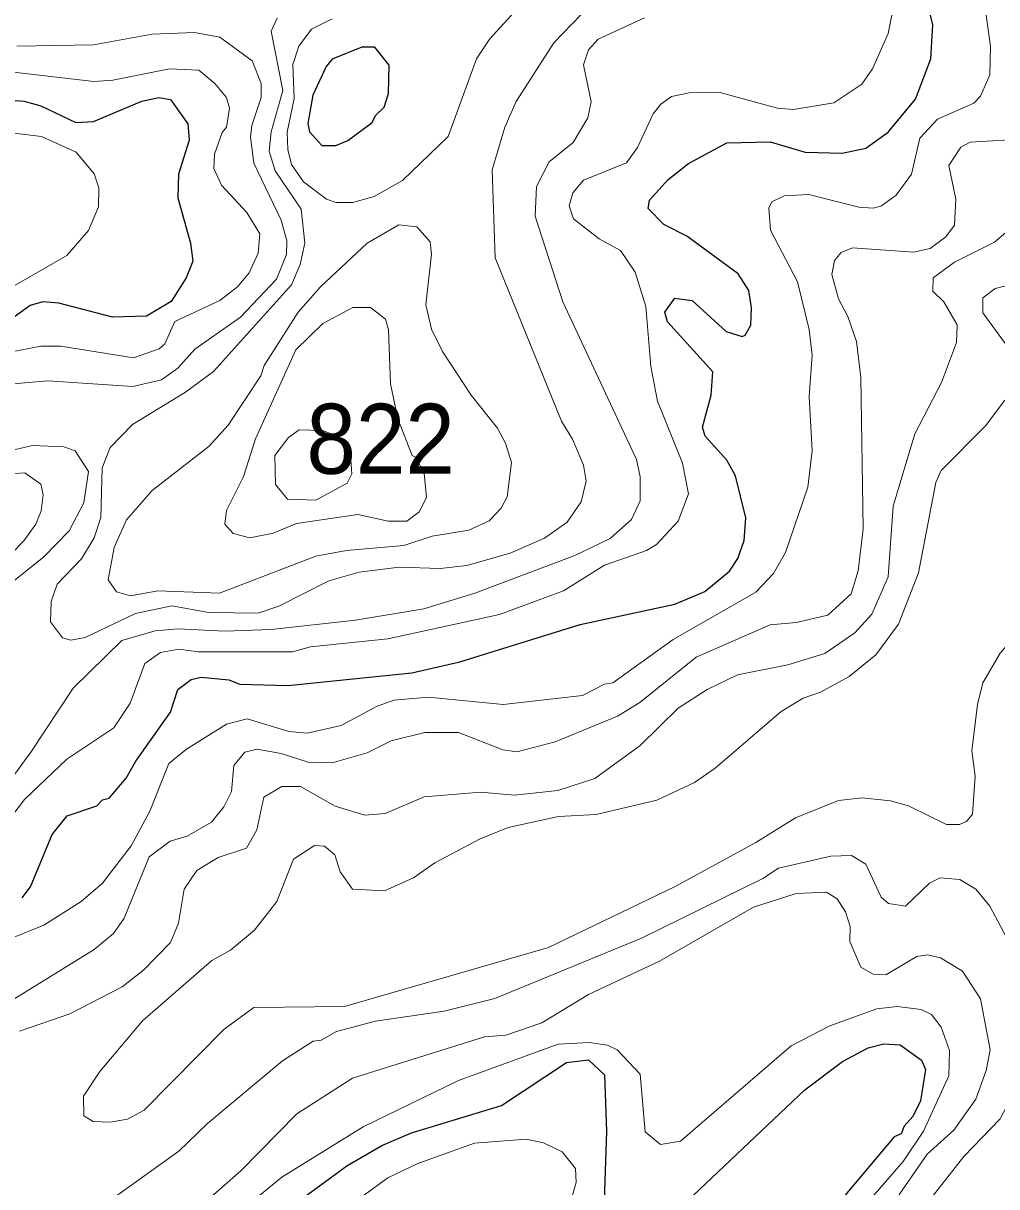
# Model space of a CAD drawing. Extents: x 763.2 to 816.8, y 7896.5 to 7952.7.
# Drawn here: x 765.256 to 767.48, y 7901.566 to 7904.224 of the extents above; entities that cross this region are included whole.
import ezdxf

# ---------------------------------------------------------------- set-up
doc = ezdxf.new("R2010")
doc.units = 0
doc.header["$LTSCALE"] = 0.064
doc.layers.add('1', color=7, linetype='Continuous', lineweight=25)
doc.layers.add('2', color=7, linetype='Continuous', lineweight=13)
doc.layers.add('21', color=7, linetype='Continuous')

msp = doc.modelspace()

# ---------------------------------------------------------------- linework, layer by layer
at = {"layer": '1'}
for points in [[(765.6395, 7902.7247), (765.6623, 7902.7301), (765.7256, 7902.7238), (765.751, 7902.7138), (765.8604, 7902.7106), (766.1439, 7902.74), (766.2539, 7902.7649), (766.5283, 7902.8502), (766.7446, 7902.8967), (766.8135, 7902.9259), (766.8698, 7902.9724), (766.889, 7903.0014), (766.9033, 7903.0424), (766.9071, 7903.0937), (766.8833, 7903.1903), (766.8634, 7903.2261), (766.8142, 7903.2803), (766.8079, 7903.3014), (766.8282, 7903.3744), (766.8315, 7903.428), (766.7278, 7903.5422), (766.7219, 7903.5643), (766.7448, 7903.5958), (766.7847, 7903.5904), (766.8622, 7903.5197), (766.8983, 7903.5087), (766.9058, 7903.5116), (766.9185, 7903.5339), (766.9202, 7903.574), (766.9136, 7903.6133), (766.8896, 7903.6515), (766.7723, 7903.7373), (766.7199, 7903.7639), (766.6839, 7903.8007), (766.6872, 7903.8197), (766.7298, 7903.8674), (766.7757, 7903.9036), (766.8638, 7903.9508), (766.9623, 7903.9529), (767.0428, 7903.9299), (767.1273, 7903.9271), (767.1816, 7903.9385), (767.2319, 7903.9755), (767.2945, 7904.0509), (767.3297, 7904.1427), (767.3344, 7904.2201), (767.311, 7904.3166)], [(765.0943, 7904.0586), (765.2579, 7904.0463), (765.2959, 7904.0352), (765.3763, 7903.9974), (765.4167, 7903.9996), (765.5267, 7904.0459), (765.5655, 7904.0546), (765.5922, 7904.0496), (765.6321, 7903.9941), (765.6348, 7903.9571), (765.6107, 7903.8789), (765.6089, 7903.8254), (765.6382, 7903.722), (765.6433, 7903.6804), (765.6285, 7903.6423), (765.5939, 7903.5882), (765.538, 7903.5547), (765.4603, 7903.5522), (765.3377, 7903.5849), (765.3008, 7903.5878), (765.2721, 7903.5795), (765.152, 7903.4928)], [(765.4522, 7902.4538), (765.4909, 7902.4991), (765.5131, 7902.5378), (765.5926, 7902.6502), (765.6093, 7902.7022), (765.6395, 7902.7247)], [(765.2539, 7902.226), (765.2723, 7902.251), (765.3219, 7902.3708), (765.3566, 7902.4131), (765.424, 7902.4359), (765.4372, 7902.4499), (765.4522, 7902.4538)], [(766.744, 7901.5053), (767.042, 7901.7868), (767.1283, 7901.8519), (767.1867, 7901.883), (767.2227, 7901.8919), (767.2596, 7901.8898), (767.3083, 7901.8553), (767.3178, 7901.8338), (767.3064, 7901.7623), (767.2884, 7901.7261), (767.2689, 7901.7045), (767.2619, 7901.6869), (767.2459, 7901.6798), (767.1171, 7901.5265)], [(765.6599, 7901.3677), (765.9953, 7901.6133), (766.0757, 7901.6602), (766.143, 7901.6888), (766.3491, 7901.7511), (766.4971, 7901.8494), (766.5479, 7901.8554), (766.5842, 7901.8213), (766.5884, 7901.6916), (766.5836, 7901.5345)]]:
    msp.add_lwpolyline(points, dxfattribs=at)
msp.add_lwpolyline([(766.0903, 7904.0638), (766.0918, 7904.1286), (766.0593, 7904.1693), (766.0297, 7904.1697), (765.962, 7904.1424), (765.9482, 7904.1255), (765.9179, 7904.0597), (765.9065, 7903.9948), (765.9103, 7903.9763), (765.9385, 7903.9449), (765.9703, 7903.9449), (765.9976, 7903.956), (766.0536, 7903.997), (766.061, 7904.0135), (766.0807, 7904.0325)], close=True, dxfattribs=at)
at = {"layer": '2'}
for points in [[(767.1084, 7904.0419), (767.1723, 7904.0851), (767.1967, 7904.1197), (767.2323, 7904.2004), (767.2556, 7904.3194), (767.2476, 7904.3788)], [(767.4496, 7904.2913), (767.4659, 7904.1715), (767.4642, 7904.1064), (767.4432, 7904.0573), (767.4281, 7904.0417), (767.3448, 7904.005), (767.3049, 7903.9619), (767.2854, 7903.8796), (767.2506, 7903.8312), (767.2168, 7903.8071), (767.1991, 7903.8018), (767.165, 7903.8038), (767.0511, 7903.8329), (766.995, 7903.83), (766.9667, 7903.8163), (766.9599, 7903.8018), (766.9631, 7903.7515), (767.0251, 7903.633), (767.0516, 7903.5246), (767.0583, 7903.4655), (767.0518, 7903.3712), (767.0584, 7903.2471), (767.0488, 7903.1638), (766.9978, 7903.0152), (766.9704, 7902.9665), (766.9301, 7902.9243), (766.7409, 7902.8164), (766.6029, 7902.7174), (766.5842, 7902.7138), (766.5339, 7902.6878), (766.3524, 7902.6678), (766.1815, 7902.6841), (766.1026, 7902.6775), (766.063, 7902.663), (765.9823, 7902.6196), (765.9047, 7902.602), (765.863, 7902.6058), (765.7675, 7902.6345), (765.7202, 7902.6229), (765.6288, 7902.5654), (765.5889, 7902.5325), (765.5454, 7902.4242), (765.5023, 7902.3445), (765.437, 7902.2594), (765.3881, 7902.2171), (765.3032, 7902.1633), (765.2277, 7902.133)], [(766.5304, 7904.2432), (766.4685, 7904.1794), (766.3824, 7904.0456), (766.3564, 7903.9868), (766.3273, 7903.8895), (766.334, 7903.688), (766.4861, 7903.315), (766.5113, 7903.2735), (766.536, 7903.2143), (766.5423, 7903.1779), (766.5311, 7903.1303), (766.4992, 7903.0839), (766.447, 7903.0474), (766.3688, 7903.0131), (766.2695, 7902.985), (766.2086, 7902.9784), (766.1151, 7902.9816), (766.0237, 7902.9702), (765.9541, 7902.9504), (765.8404, 7902.8919), (765.7929, 7902.8765), (765.6804, 7902.8778), (765.5958, 7902.8928), (765.5125, 7902.8754), (765.3978, 7902.8204), (765.3646, 7902.8142), (765.3454, 7902.8201), (765.3186, 7902.8561), (765.3199, 7902.9026), (765.3334, 7902.9423), (765.389, 7903.0004), (765.4184, 7903.048), (765.4331, 7903.0949), (765.4364, 7903.2084), (765.4548, 7903.2544), (765.5054, 7903.307), (765.6265, 7903.3813), (765.6905, 7903.4281), (765.8688, 7903.6265), (765.8891, 7903.6727), (765.8997, 7903.7213), (765.8914, 7903.7993), (765.8317, 7903.8869), (765.8177, 7903.9322), (765.8222, 7903.976), (765.8488, 7904.0703), (765.8228, 7904.2057), (765.836, 7904.2354)], [(766.387, 7904.2592), (766.3225, 7904.1884), (766.2916, 7904.143), (766.227, 7903.9651), (766.1227, 7903.8651), (766.0581, 7903.8283), (766.0092, 7903.8149), (765.9712, 7903.8149), (765.9486, 7903.8225), (765.8961, 7903.8614), (765.869, 7903.9013), (765.8603, 7903.9355), (765.8589, 7903.9754), (765.8751, 7904.0524), (765.872, 7904.1299), (765.8854, 7904.1721), (765.9145, 7904.2103), (765.962, 7904.2345)], [(765.1323, 7902.367), (765.2732, 7902.5587), (765.3703, 7902.7049), (765.4815, 7902.8141), (765.5577, 7902.8355), (765.61, 7902.8403), (765.7158, 7902.8353), (765.8228, 7902.8391), (766.0155, 7902.8604), (766.1716, 7902.8865), (766.288, 7902.922), (766.5167, 7903.0082), (766.597, 7903.0467), (766.6459, 7903.0902), (766.6659, 7903.133), (766.6657, 7903.188), (766.6576, 7903.2275), (766.4893, 7903.5878), (766.4259, 7903.783), (766.4288, 7903.8513), (766.458, 7903.9071), (766.5128, 7903.9513), (766.5464, 7904.0082), (766.5536, 7904.0442), (766.536, 7904.1292), (766.5473, 7904.163), (766.5695, 7904.1878), (766.6759, 7904.2366)], [(765.2415, 7904.1715), (765.4164, 7904.1749), (765.5504, 7904.1994), (765.6477, 7904.2027), (765.7056, 7904.1923), (765.7794, 7904.1386), (765.7995, 7904.0865), (765.7995, 7904.0541), (765.7782, 7903.9907), (765.7754, 7903.9636), (765.7827, 7903.9042), (765.8452, 7903.7744), (765.8583, 7903.7266), (765.8575, 7903.696), (765.8346, 7903.639), (765.7523, 7903.5526), (765.6484, 7903.4796), (765.6094, 7903.4358), (765.5722, 7903.4091), (765.5064, 7903.3942), (765.3124, 7903.4072), (765.2328, 7903.4005)], [(765.2139, 7904.1144), (765.4176, 7904.0911), (765.4611, 7904.0942), (765.5904, 7904.1203), (765.657, 7904.1172), (765.6938, 7904.0865)], [(765.6938, 7904.0865), (765.7203, 7904.0544), (765.7273, 7904.0298), (765.7205, 7903.9865), (765.7105, 7903.9747), (765.6929, 7903.9249)], [(765.1559, 7902.3167), (765.2589, 7902.4507), (765.3554, 7902.5425), (765.4634, 7902.6144), (765.5001, 7902.6707), (765.5342, 7902.7616), (765.5695, 7902.7863), (765.6114, 7902.7943), (765.6568, 7902.7878), (765.8711, 7902.7878), (765.912, 7902.7992), (766.0888, 7902.8173), (766.3445, 7902.873), (766.4908, 7902.9274), (766.5839, 7902.9858), (766.6798, 7903.0193), (766.703, 7903.0331), (766.7523, 7903.0863), (766.7757, 7903.1486), (766.7627, 7903.2188), (766.705, 7903.3603), (766.6901, 7903.44), (766.6785, 7903.5772), (766.6541, 7903.6554), (766.6205, 7903.7052), (766.5723, 7903.7319), (766.5131, 7903.7773), (766.5033, 7903.8072), (766.5121, 7903.8363), (766.536, 7903.8657), (766.6342, 7903.9054), (766.6593, 7903.9399), (766.6952, 7904.0169), (766.7132, 7904.0395), (766.737, 7904.0565), (766.7779, 7904.0654), (766.8457, 7904.0665), (766.9796, 7904.0302), (767.0156, 7904.0271), (767.1084, 7904.0419)], [(765.4281, 7903.8047), (765.429, 7903.8481), (765.4183, 7903.8797), (765.3772, 7903.9296), (765.2974, 7903.9657), (765.1593, 7903.9824)], [(765.1497, 7901.9427), (765.4182, 7902.1074), (765.4621, 7902.1447), (765.4868, 7902.1791), (765.544, 7902.3198), (765.5919, 7902.355), (765.6305, 7902.3666), (765.686, 7902.3987), (765.7141, 7902.4339), (765.7319, 7902.4685), (765.7375, 7902.5282), (765.762, 7902.5589), (765.7897, 7902.5657), (765.8455, 7902.5559), (765.907, 7902.5358), (765.9616, 7902.5344), (766.042, 7902.5575), (766.0967, 7902.5843), (766.1736, 7902.6035), (766.2509, 7902.6034), (766.3517, 7902.5642), (766.3839, 7902.5593), (766.4711, 7902.5823), (766.6135, 7902.6408), (766.6651, 7902.6719), (766.7939, 7902.776), (766.9624, 7902.8498), (767.0222, 7902.8551), (767.0944, 7902.8718), (767.1476, 7902.9202), (767.1638, 7902.9732), (767.175, 7903.069), (767.1701, 7903.4148), (767.1596, 7903.4967), (767.1402, 7903.5541), (767.1188, 7903.5944), (767.1033, 7903.6498), (767.1095, 7903.6818), (767.1251, 7903.7003), (767.1505, 7903.7112), (767.2902, 7903.7014), (767.3285, 7903.7095), (767.3641, 7903.736), (767.3836, 7903.763), (767.3871, 7903.8224), (767.3707, 7903.899), (767.3982, 7903.9408), (767.4195, 7903.9525), (767.5482, 7903.9603)], [(765.6929, 7903.9249), (765.6913, 7903.8922), (765.7093, 7903.8543), (765.7666, 7903.7918), (765.7967, 7903.7433), (765.7931, 7903.6988), (765.7724, 7903.6535), (765.7458, 7903.6215), (765.7053, 7903.5905), (765.6023, 7903.543), (765.5793, 7903.4917), (765.5668, 7903.4801), (765.5077, 7903.46), (765.3419, 7903.4861), (765.2966, 7903.4861), (765.2252, 7903.4722)], [(764.8562, 7903.4334), (765.099, 7903.5656), (765.2249, 7903.6181), (765.3558, 7903.6933), (765.405, 7903.7506), (765.4281, 7903.8047)], [(767.5116, 7903.7551), (767.4752, 7903.7241), (767.384, 7903.6783), (767.3351, 7903.6426), (767.3345, 7903.6118), (767.3594, 7903.5875), (767.3901, 7903.5352), (767.3886, 7903.4945), (767.3544, 7903.403), (767.2929, 7903.2859), (767.2439, 7903.1206), (767.2325, 7902.9592), (767.1951, 7902.8738), (767.1558, 7902.831), (767.0873, 7902.7843), (767.0032, 7902.7584), (766.8882, 7902.7351), (766.8185, 7902.7022), (766.7522, 7902.659), (766.6656, 7902.5741), (766.5621, 7902.4985), (766.4773, 7902.4708), (766.3787, 7902.4607), (766.3006, 7902.4671), (766.1718, 7902.4565), (766.0829, 7902.4182), (766.0362, 7902.4147), (765.9686, 7902.4354), (765.8898, 7902.4802), (765.847, 7902.4804), (765.8055, 7902.4558), (765.7897, 7902.3809), (765.7664, 7902.3394), (765.7016, 7902.3178), (765.6524, 7902.2884), (765.6238, 7902.2453), (765.6109, 7902.1679), (765.5923, 7902.1238), (765.5306, 7902.0602), (765.4819, 7902.0222), (765.3624, 7901.9611), (765.2474, 7901.9215)], [(767.5087, 7903.4805), (767.4488, 7903.5621), (767.4484, 7903.5964), (767.4765, 7903.6178), (767.6043, 7903.6493)], [(767.4487, 7902.7168), (767.4362, 7902.6679), (767.4237, 7902.562), (767.4313, 7902.5038), (767.4249, 7902.4171), (767.4115, 7902.3999), (767.3953, 7902.3933), (767.3652, 7902.3936), (767.2786, 7902.436), (767.2378, 7902.4478), (767.1732, 7902.4541), (767.1186, 7902.4484), (767.0204, 7902.4087), (766.9296, 7902.3519), (766.7468, 7902.2523), (766.4562, 7902.1121), (765.9902, 7901.9775), (765.7827, 7901.9754), (765.7152, 7901.926), (765.5327, 7901.7405), (765.4944, 7901.7198), (765.4544, 7901.7129), (765.4158, 7901.7146), (765.3946, 7901.7278), (765.3937, 7901.7728), (765.4308, 7901.8291), (765.5287, 7901.9448), (765.6866, 7902.0827), (765.7294, 7902.106), (765.7848, 7902.1517), (765.8357, 7902.2177), (765.8739, 7902.3143), (765.9212, 7902.3453), (765.9445, 7902.3435), (765.9683, 7902.3243), (765.98, 7902.2852), (766.0085, 7902.2457), (766.0815, 7902.242), (766.1479, 7902.2717), (766.1967, 7902.3057), (766.2985, 7902.3601), (766.3642, 7902.3864), (766.4791, 7902.4117), (766.5654, 7902.4163), (766.7034, 7902.4492), (766.7901, 7902.4895), (766.837, 7902.5219), (766.9878, 7902.6513), (767.0382, 7902.6821), (767.0776, 7902.6954), (767.1435, 7902.7313), (767.204, 7902.7807), (767.2559, 7902.8508), (767.3015, 7902.9686), (767.341, 7903.1748), (767.3536, 7903.202), (767.4544, 7903.3041), (767.4987, 7903.363)], [(765.1987, 7903.2413), (765.2769, 7903.2593), (765.3486, 7903.256), (765.3746, 7903.2473), (765.4051, 7903.2003), (765.3947, 7903.1282), (765.3611, 7903.0644), (765.3031, 7903.0046), (765.2145, 7902.9339)], [(765.2366, 7903.1954), (765.2599, 7903.1968), (765.2961, 7903.1709), (765.3014, 7903.1466), (765.2968, 7903.1104), (765.2847, 7903.0797), (765.2575, 7903.0414), (765.0436, 7902.8222)], [(767.6077, 7903.0918), (767.6926, 7902.9809), (767.6931, 7902.9371), (767.5384, 7902.8435), (767.4878, 7902.785), (767.4487, 7902.7168)], [(765.4263, 7901.5142), (765.6116, 7901.6468), (765.6768, 7901.71), (765.8483, 7901.8537), (765.9181, 7901.8984), (765.9368, 7901.9004), (765.9717, 7901.9202), (766.0611, 7901.9443), (766.2179, 7901.9672), (766.3335, 7901.996), (766.6683, 7902.1334), (766.946, 7902.2698), (766.9816, 7902.2939), (767.1011, 7902.3209), (767.1483, 7902.3223), (767.1812, 7902.3026), (767.2165, 7902.2275), (767.2334, 7902.2127), (767.2718, 7902.207), (767.3265, 7902.2594)], [(767.3265, 7902.2594), (767.3512, 7902.2714), (767.396, 7902.2676), (767.4325, 7902.2458), (767.4646, 7902.2069), (767.5036, 7902.1336)], [(767.2441, 7901.5288), (767.321, 7901.6399), (767.382, 7901.6948), (767.4323, 7901.7658), (767.4561, 7901.8312), (767.4655, 7901.8784), (767.4431, 7901.9949), (767.4018, 7902.058), (767.3521, 7902.0885), (767.3225, 7902.0956), (767.2979, 7902.0921), (767.2267, 7902.05), (767.1977, 7902.0513), (767.1697, 7902.0674), (767.1444, 7902.1257), (767.1453, 7902.16), (767.135, 7902.1941), (767.1159, 7902.2238), (767.0911, 7902.2385), (767.0222, 7902.2355), (766.9243, 7902.2045), (766.71, 7902.0811), (766.5477, 7902.0047), (766.4411, 7901.9401), (766.359, 7901.912), (766.3097, 7901.9085), (766.0086, 7901.8139), (765.8813, 7901.7321), (765.7529, 7901.6023), (765.6422, 7901.5046)], [(767.5036, 7902.1336), (767.571, 7901.9233), (767.5483, 7901.8352), (767.4881, 7901.7208), (767.4053, 7901.6348), (767.3132, 7901.5173)], [(765.702, 7901.469), (765.8472, 7901.5879), (766.0324, 7901.7026), (766.2505, 7901.8084), (766.4785, 7901.8916), (766.5489, 7901.8953), (766.5911, 7901.8889), (766.6133, 7901.8789), (766.6654, 7901.8229), (766.6767, 7901.6908), (766.7119, 7901.6623), (766.7574, 7901.6699), (767.0105, 7901.8878), (767.0989, 7901.9331), (767.2063, 7901.9725), (767.253, 7901.9773), (767.3076, 7901.9709), (767.331, 7901.9592), (767.3536, 7901.9302), (767.3722, 7901.8772), (767.3705, 7901.8189), (767.3128, 7901.6927), (767.2666, 7901.6236), (767.1468, 7901.4855)], [(766.4964, 7901.497), (766.5194, 7901.5751), (766.5175, 7901.6076), (766.4877, 7901.6455), (766.4451, 7901.6661), (766.405, 7901.6748), (766.2874, 7901.6655), (766.1578, 7901.6192), (766.0888, 7901.5863), (765.9994, 7901.5208)]]:
    msp.add_lwpolyline(points, dxfattribs=at)
for points in [[(766.1759, 7903.5805), (766.1889, 7903.6964), (766.1859, 7903.725), (766.1553, 7903.7587), (766.1141, 7903.7637), (766.0418, 7903.7218), (765.9355, 7903.622), (765.884, 7903.5637), (765.8066, 7903.4424), (765.7991, 7903.4182), (765.7244, 7903.3059), (765.6806, 7903.2575), (765.5508, 7903.1568), (765.4917, 7903.0898), (765.4638, 7903.0263), (765.4503, 7902.9522), (765.4689, 7902.9248), (765.5012, 7902.9159), (765.5637, 7902.9273), (765.7047, 7902.9216), (765.9247, 7903.0067), (765.9948, 7903.0196), (766.1256, 7903.0312), (766.1901, 7903.052), (766.2742, 7903.0658), (766.3206, 7903.0872), (766.3483, 7903.1165), (766.3614, 7903.1418), (766.3713, 7903.2208), (766.3583, 7903.2643), (766.3393, 7903.2991), (766.2795, 7903.3744), (766.214, 7903.474), (766.1886, 7903.5253)], [(765.8786, 7903.4779), (765.9405, 7903.5378), (766.0093, 7903.5749), (766.0491, 7903.5747), (766.0841, 7903.5479), (766.0907, 7903.5234), (766.0952, 7903.4005), (766.1118, 7903.3203), (766.1443, 7903.2362), (766.1522, 7903.233), (766.1721, 7903.1961), (766.1774, 7903.1402), (766.1606, 7903.1079), (766.1323, 7903.0866), (766.0895, 7903.0868), (766.0204, 7903.1014), (765.8805, 7903.0808), (765.8267, 7903.0592), (765.7738, 7903.0482), (765.7357, 7903.058), (765.7167, 7903.0793), (765.7204, 7903.1109), (765.7596, 7903.1882), (765.7866, 7903.2748)], [(765.8621, 7903.2777), (765.8863, 7903.2951), (765.94, 7903.2938), (765.9702, 7903.282), (766.0031, 7903.2456), (766.0068, 7903.1944), (765.996, 7903.1734), (765.9248, 7903.1347), (765.8597, 7903.1366), (765.8324, 7903.17), (765.8312, 7903.2361)]]:
    msp.add_lwpolyline(points, close=True, dxfattribs=at)

# ---------------------------------------------------------------- texts
at = {"layer": '21', "width": 0.95}
msp.add_text('822', height=0.16, dxfattribs=at).set_placement((765.9031, 7903.1947))

doc.saveas('drawing.dxf')
